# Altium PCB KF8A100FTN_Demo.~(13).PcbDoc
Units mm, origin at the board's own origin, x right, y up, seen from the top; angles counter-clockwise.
Board outline 152.4 x 101.6 mm, 2 copper layers (Top Layer, Bottom Layer); 25 components, 0 nets, 113 pads, 0 vias.
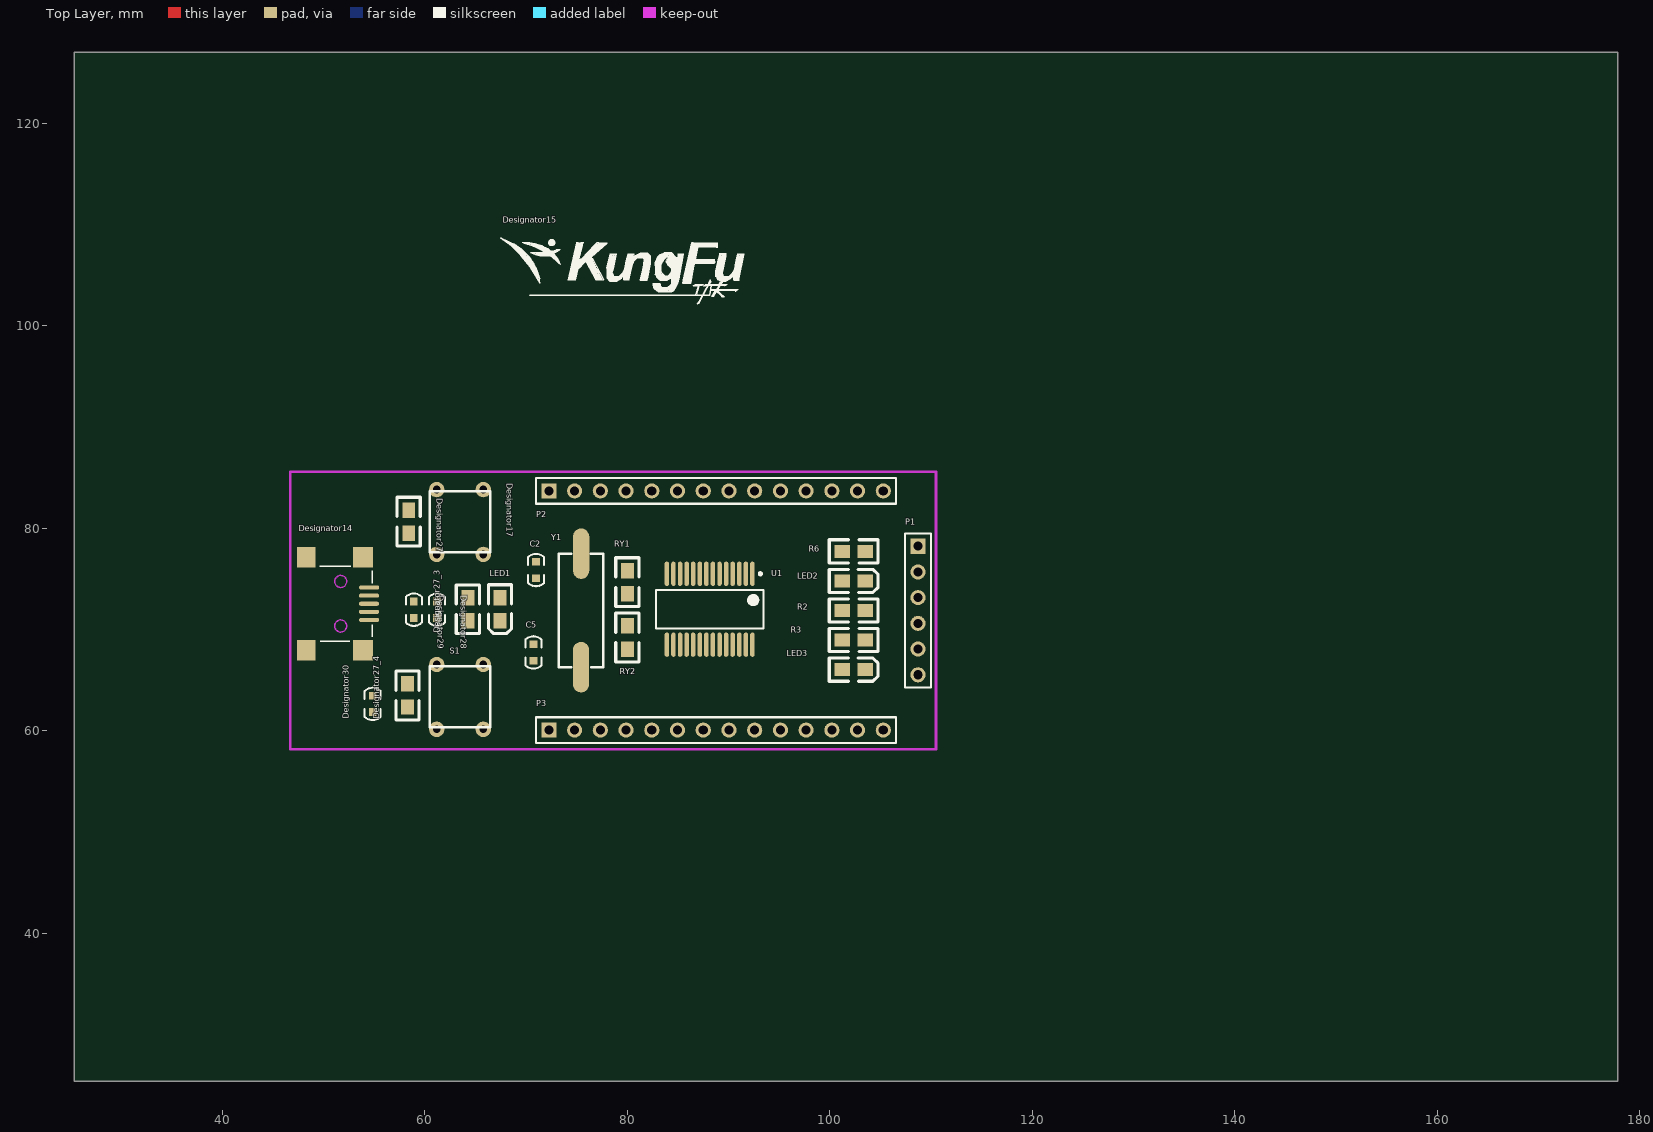
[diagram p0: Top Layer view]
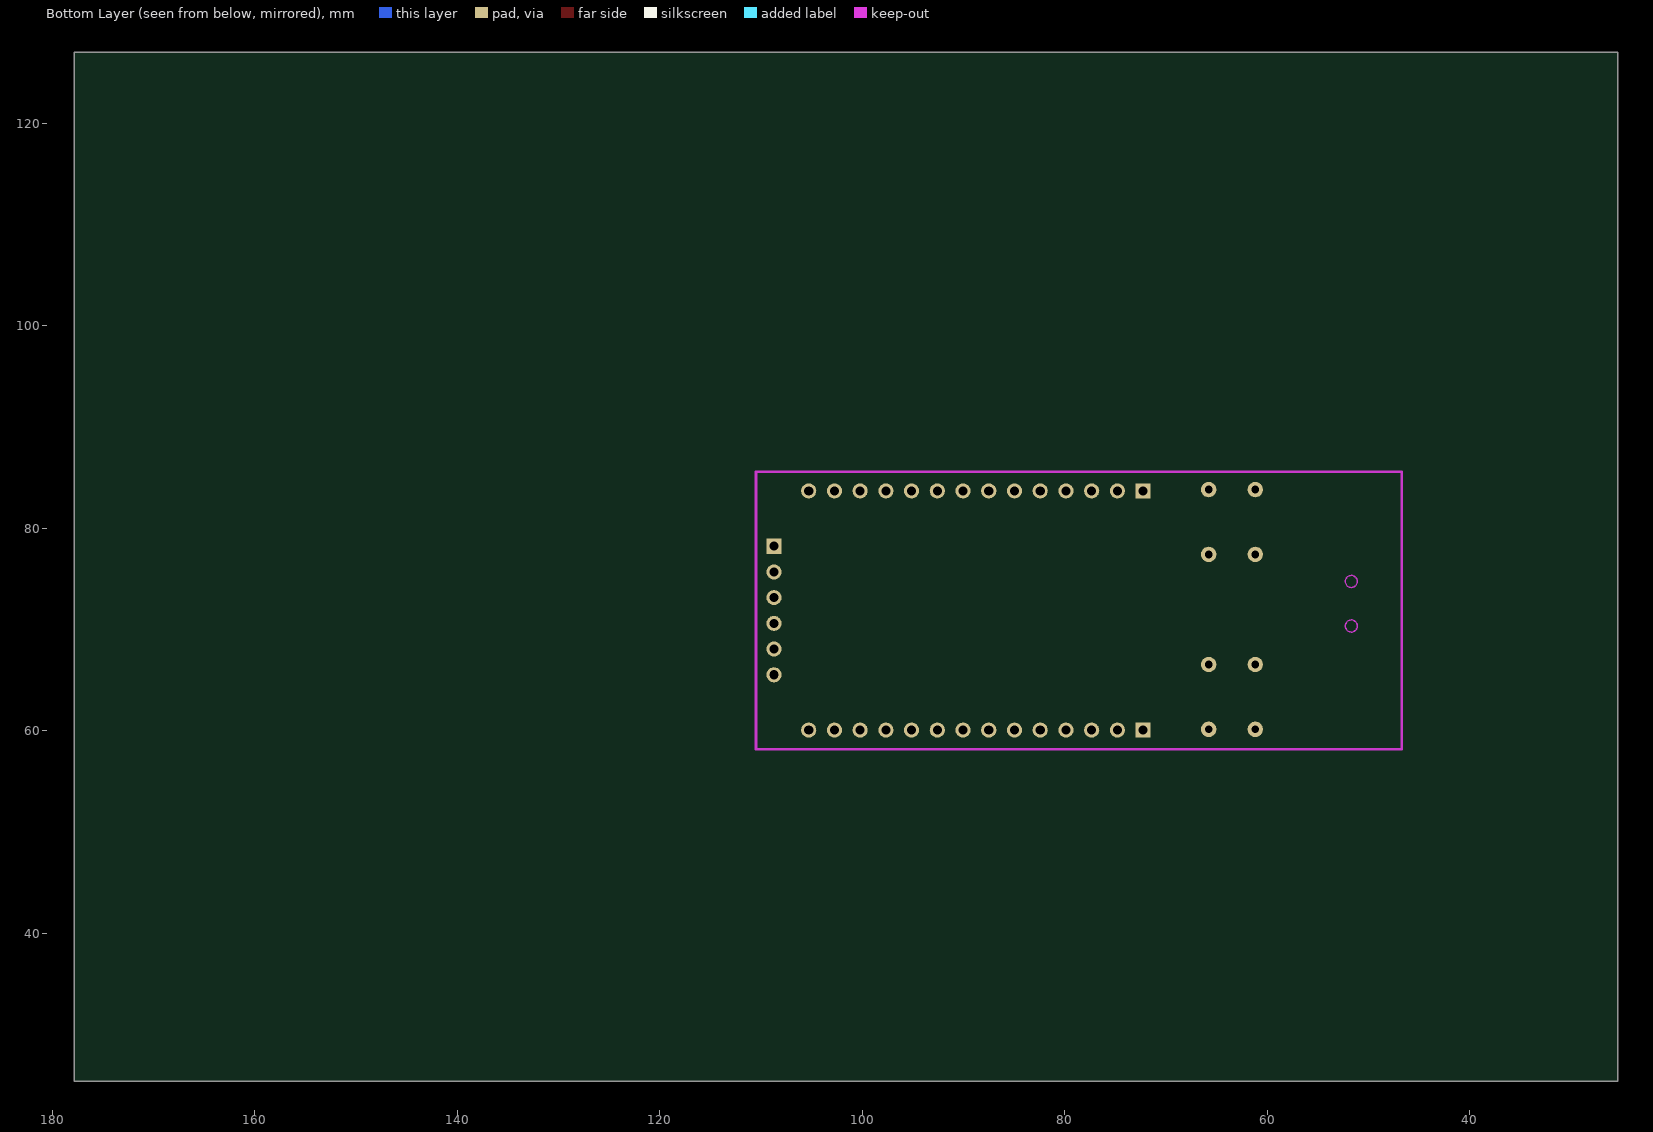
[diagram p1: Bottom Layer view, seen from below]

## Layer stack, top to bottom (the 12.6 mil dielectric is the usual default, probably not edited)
Top Solder: solder mask 0.0102, Solder Resist, Dk 3.5
Top Layer: signal copper 0.0356
Dielectric 1: dielectric 0.32, FR-4, Dk 4.8
Bottom Layer: signal copper 0.0356
Bottom Solder: solder mask 0.0102, Solder Resist, Dk 3.5

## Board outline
25.4,25.4 177.8,25.4 177.8,127 25.4,127

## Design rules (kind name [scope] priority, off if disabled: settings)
Clearance [All] p1: gap=0.254
PolygonConnect [All] p1: connectstyle=Relief reliefconductorwidth=0.254 reliefentries=4 polygonreliefangle="90 Angle" airgapwidth=0.254
RoutingVias [All] p1: holewidth=0.711 width=1.27 viastyle="Through Hole" minholewidth=0.711 minwidth=1.27 maxholewidth=0.711 maxwidth=1.27
SolderMaskExpansion [All] p1: expansion=0.102
UnpouredPolygon [All] p1: allowunpoured=FALSE
Width [All] p1: maxlimit=0.254 minlimit=0.254 preferedwidth=0.254
29 further rules are at their usual default settings.

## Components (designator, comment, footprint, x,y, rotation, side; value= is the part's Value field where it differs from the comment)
C2 "Comment" 0603C 70.993,75.057 r90 top
C5 "Comment" 0603C 70.739,66.929 r90 top
Designator14 "Comment" USB_MINI_B 51.562,73.406 r0 top
Designator15 "Comment" LOGO 70.358,102.997 r0 top
Designator17 "Comment" KEY6*6 65.786,83.82 r270 top
Designator27 "Comment" 0805 58.42,81.788 r270 top
Designator27_3 "Comment" 0805 64.262,70.866 r90 top
Designator27_4 "Comment" 0805 58.293,62.357 r90 top
Designator28 "Comment" 0603C 61.214,72.771 r270 top
Designator29 "Comment" 0603C 58.928,72.771 r270 top
Designator30 "Comment" 0603C 54.864,61.849 r90 top
LED1 "Comment" D0805 67.437,73.152 r270 top
LED2 "Comment" D0805 101.216,74.803 r0 top
LED3 "Comment" D0805 101.216,66.04 r0 top
P1 "Comment" HDR1X6 108.712,78.232 r270 top
P2 "Comment" HDR1X14 72.263,83.693 r0 top
P3 "Comment" HDR1X14 72.263,60.071 r0 top
R2 "Comment" 0805 101.219,71.882 r0 top
R3 "Comment" 0805 101.219,68.961 r0 top
R6 "Comment" 0805 101.219,77.724 r0 top
RY1 "Comment" 0805 80.01,75.819 r270 top
RY2 "Comment" 0805 80.01,70.358 r270 top
S1 "Comment" KEY6*6 65.786,66.548 r270 top
U1 "Comment" SSOP-SS28_M 88.138,72.009 r270 top
Y1 "Comment" CRYSTAL 75.438,66.294 r90 top

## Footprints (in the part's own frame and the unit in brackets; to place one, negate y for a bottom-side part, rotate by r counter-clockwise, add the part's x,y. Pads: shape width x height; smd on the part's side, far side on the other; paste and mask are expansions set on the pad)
0603C [mil]
  rect 30x30 smd: 1(0,0) 2(64,0)
  silkscreen extent -31,-31 95,31
0805 [mil]
  rect 60x50 smd: 1(-0.11,0) 2(89.89,0)
  silkscreen extent -50,-45 140,45
CRYSTAL [mm]
  oval 5x1.6 smd: 1(0,0) 2(11.2,-0.01)
  silkscreen extent 0,-2.2 11.2,2.2
D0805 [mil]
  rect 60x50 smd: 1(0,0) 2(90,0)
  silkscreen extent -50,-45 140,45
HDR1X6 [mm] "Connector; Header; 6 Position"
  rect 1.5x1.5 hole 0.9: 1(0,0)
  round 1.5 hole 0.9: 2(2.54,0) 3(5.08,0) 4(7.62,0) 5(10.16,0) 6(12.7,0)
  silkscreen extent -1.27,-1.27 13.97,1.27
HDR1X14 [mm] "Connector; Header; 14 Position"
  rect 1.5x1.5 hole 0.9: 1(0,0)
  round 1.5 hole 0.9: 2(2.54,0) 3(5.08,0) 4(7.62,0) 5(10.16,0) 6(12.7,0) 7(15.24,0) 8(17.78,0) 9(20.32,0) 10(22.86,0) 11(25.4,0) 12(27.94,0) 13(30.48,0) 14(33.02,0)
  silkscreen extent -1.27,-1.27 34.29,1.27
KEY6*6 [mil]
  round 60 hole 30: 1(0,0) 2(0,-181.1) 3(251.97,0) 4(251.97,-181.1)
  silkscreen extent 7,-209 243,28
LOGO [mm]
  silkscreen extent -2.9,-0.84 21.21,5.71
SSOP-SS28_M [mm] "SOP, 28-Leads, Body 10.2x5.2mm, Pitch 0.65mm, IPC Low Density"
  oval 2.4x0.45 smd: 1(-3.5,4.225) 2(-3.5,3.575) 3(-3.5,2.925) 4(-3.5,2.275) 5(-3.5,1.625) 6(-3.5,0.975) 7(-3.5,0.325) 8(-3.5,-0.325) 9(-3.5,-0.975) 10(-3.5,-1.625) 11(-3.5,-2.275) 12(-3.5,-2.925) 13(-3.5,-3.575) 14(-3.5,-4.225) 15(3.5,-4.225) 16(3.5,-3.575) 17(3.5,-2.925) 18(3.5,-2.275) 19(3.5,-1.625) 20(3.5,-0.975) 21(3.5,-0.325) 22(3.5,0.325) 23(3.5,0.975) 24(3.5,1.625) 25(3.5,2.275) 26(3.5,2.925) 27(3.5,3.575) 28(3.5,4.225)
  silkscreen extent -3.62,-5.3 1.9,5.3, body extent -2.7,-5.3 2.7,5.3, height 2
USB_MINI_B [mm] "USB_MINI_B"
  oval 2x0.4 smd: 1(2.941,0.744) 2(2.941,-0.056) 3(2.941,-0.856) 4(2.941,-1.656) 5(2.941,-2.456)
  rect 1.797x2 smd: 6(-3.259,-5.456) 6(-3.259,3.744)
  rect 2x2 smd: 6(2.341,-5.456) 6(2.341,3.744)
  Keep-Out Layer circle w0.127: c0.141,1.344 r0.6
  Keep-Out Layer circle w0.127: c0.141,-3.056 r0.6
  silkscreen extent -1.93,-4.58 3.24,2.85

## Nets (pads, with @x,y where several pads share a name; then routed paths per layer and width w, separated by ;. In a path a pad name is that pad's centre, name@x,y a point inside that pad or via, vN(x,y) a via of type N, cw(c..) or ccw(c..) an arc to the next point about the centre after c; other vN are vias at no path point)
pads on no net: C2.1 C2.2 C5.1 C5.2 Designator14.1 Designator14.2 Designator14.3 Designator14.4 Designator14.5 Designator14.6 Designator17.1 Designator17.2 Designator17.3 Designator17.4 Designator27.1 Designator27.2 Designator27_3.1 Designator27_3.2 Designator27_4.1 Designator27_4.2 Designator28.1 Designator28.2 Designator29.1 Designator29.2 Designator30.1 Designator30.2 LED1.1 LED1.2 LED2.1 LED2.2 LED3.1 LED3.2 P1.1 P1.2 P1.3 P1.4 P1.5 P1.6 P2.1 P2.2 P2.3 P2.4 P2.5 P2.6 P2.7 P2.8 P2.9 P2.10 P2.11 P2.12 P2.13 P2.14 P3.1 P3.2 P3.3 P3.4 P3.5 P3.6 P3.7 P3.8 P3.9 P3.10 P3.11 P3.12 P3.13 P3.14 R2.1 R2.2 R3.1 R3.2 R6.1 R6.2 RY1.1 RY1.2 RY2.1 RY2.2 S1.1 S1.2 S1.3 S1.4 U1.1 U1.2 U1.3 U1.4 U1.5 U1.6 U1.7 U1.8 U1.9 U1.10 U1.11 U1.12 U1.13 U1.14 U1.15 U1.16 U1.17 U1.18 U1.19 U1.20 U1.21 U1.22 U1.23 U1.24 U1.25 U1.26 U1.27 U1.28 Y1.1 Y1.2

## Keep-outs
Keep-Out Layer:
  lines w0.254: 46.736,58.166 110.49,58.166 110.49,85.598 46.736,85.598 46.736,58.166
